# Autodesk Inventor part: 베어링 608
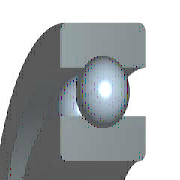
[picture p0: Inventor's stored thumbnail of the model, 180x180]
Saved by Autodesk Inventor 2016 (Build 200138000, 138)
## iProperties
IsCustomPart: 1
Created: 2012-02
Part Number: 베어링 608
Material: 강철, 연강
Description: 깊은 그루브 볼 베어링
Document SubType Name: Modeling
Standard: KS B 2023
Designer: mduedu
Standards Organization: KS
Language: ko-KR
Size Designation: 608 - 8 x 22 x 7
Categories: <MemberInstance><Categories><Category DisplayName="샤프트 부품" InternalName="7f7aeb1f-a693-4053-b835-cee3144e0d98" Mnemonic="SHFT"><Category DisplayName="베어링" Inter
Density: 7.85 g/cm^3
Appearance: 주황색
Mass: 12.145 g
Surface Area: 20.0754 cm^2
Volume: 1.54714 cm^3
Author: mduedu
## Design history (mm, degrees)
sketch "스케치" dims "d0" = 3.64 (= -0.26 x WD + 0.26 x BD)
  geometry: L1 (1.68, 7.5)-(5.32, 7.5); L2 (3.5, 7.5)-(3.5, 5.68); L3 (3.5, 7.5)-(3.5, 9.32); L4 (2.148, 6.282)-(0, 6.282); L5 (0, 4)-(7, 4); L6 (2.148, 8.718)-(0, 8.718); L7 (0, 11)-(7, 11); L8 (7, 4)-(7, 6.282); L9 (4.852, 6.282)-(7, 6.282); L10 (4.852, 8.718)-(7, 8.718); L11 (7, 11)-(7, 8.718); L12 (-1.4, 0)-(8.4, 0) reference; L13 (0, -0.3)-(0, 5.3) reference
  constraints: 22 end point, 4 point on line, 2 collinear, 2 perpendicular, 2 symmetric about line, 1 midpoint, 1 parallel, 14 other
  dimensions: "d9" = 8 diameter of L5 L12 (= WD); "d11" = 22 diameter of L7 L12 (= BD); "d12" = 7 distance between parallel lines of L8 L13 (= KB); "d13" = 12.564 diameter of L9 L12 (= 0.326 x BD + 0.674 x WD)
revolve "본체" stored, may be unused: angle "d6" = 90 deg
revolve "볼" stored, may be unused: angle "d7" = 90 deg
pattern_circular "IDS_ARRAYBALL[SIMPL:T]" dims angle "d3" = 360 deg
body "Solid1"
fillet "모깎기1" dims "d1" = 0.3 (= KRS)
other parameters: "WD" = 8 [user parameter; used in 5 equation terms], "BD" = 22 [user parameter; used in 5 equation terms], "KB" = 7 [user parameter; used in 1 equation term], "KRS" = 0.3 [user parameter; used in 1 equation term], "d4" = 0, "d5" = 0, "d8" = 0, "d14" = 0, "d15" = 0, "BBA" = 0 [user parameter], "BC0" = 1370000 [user parameter], "BC" = 3250000 [user parameter], "BR" = 11 (= 0.5 x BD) [user parameter], "WR" = 4 (= 0.5 x WD) [user parameter]
